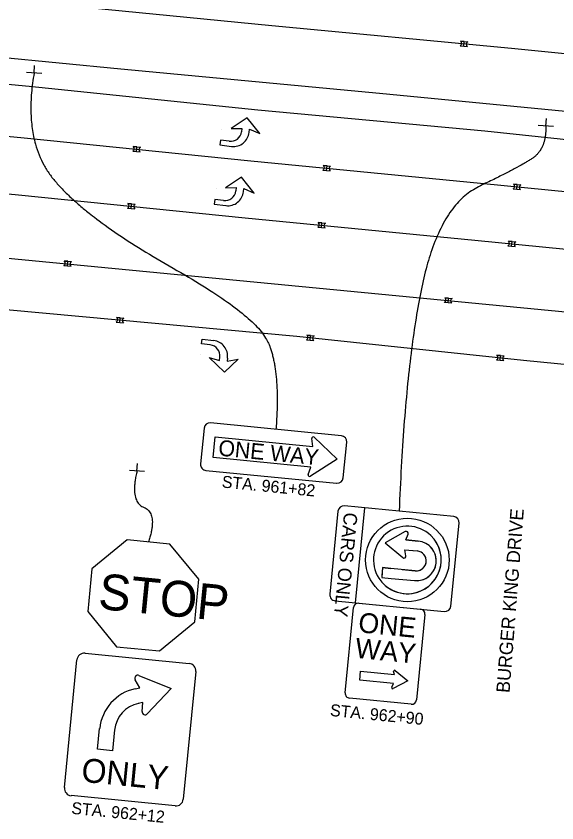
# Model space of a CAD drawing. Extents: x 1847379 to 1850904, y 217032 to 220169.
# Drawn here: x 1850312.9 to 1850426.1, y 218600.3 to 218769.3 of the extents above; entities that cross this region are included whole.
import ezdxf

# ---------------------------------------------------------------- set-up
doc = ezdxf.new("R2010")
doc.units = 0
for name, color, linetype in [('PM_P_Cells', 7, 'Continuous'), ('PM_P_Channelizing_Line', 7, 'Continuous'), ('PM_P_Edge_Line', 7, 'Continuous'), ('PM_P_Lane_Line', 7, 'Continuous'), ('SN_X_Public', 7, 'Continuous'), ('SN_X_Text', 7, 'Continuous')]:
    doc.layers.add(name, color=color, linetype=linetype)

msp = doc.modelspace()

# ---------------------------------------------------------------- linework, layer by layer
at = {"layer": 'PM_P_Cells'}
for p, q in [((1850406.66, 218764.02), (1850405.89, 218764.09)), ((1850405.89, 218764.09), (1850406.66, 218764.02)), ((1850406.57, 218763.04), (1850406.66, 218764.02)), ((1850406.66, 218764.02), (1850407.43, 218763.95)), ((1850405.81, 218763.11), (1850406.57, 218763.04)), ((1850405.81, 218763.11), (1850406.57, 218763.04)), ((1850406.57, 218763.04), (1850407.34, 218762.98)), ((1850361.22, 218748.03), (1850357.88, 218745.75)), ((1850363.88, 218744.7), (1850361.22, 218748.03)), ((1850355.94, 218745.64), (1850355.94, 218745.64)), ((1850357.88, 218745.75), (1850360.15, 218745.81)), ((1850360.15, 218745.81), (1850360.06, 218745.11)), ((1850361.66, 218744.96), (1850361.74, 218745.62)), ((1850361.74, 218745.62), (1850363.88, 218744.7)), ((1850363.88, 218744.7), (1850363.88, 218744.7)), ((1850338.15, 218741.92), (1850337.39, 218741.99)), ((1850337.39, 218741.99), (1850338.15, 218741.92)), ((1850355.66, 218743.33), (1850355.54, 218742.33)), ((1850355.54, 218742.33), (1850358, 218742.04)), ((1850357.51, 218743.11), (1850355.66, 218743.33)), ((1850337.3, 218741.01), (1850338.07, 218740.95)), ((1850337.3, 218741.01), (1850338.07, 218740.95)), ((1850338.07, 218740.95), (1850338.15, 218741.92)), ((1850338.07, 218740.95), (1850338.83, 218740.88)), ((1850338.15, 218741.92), (1850338.92, 218741.85)), ((1850377.1, 218737.05), (1850377.87, 218736.98)), ((1850377.1, 218737.05), (1850377.87, 218736.98)), ((1850377.96, 218737.95), (1850377.19, 218738.02)), ((1850377.19, 218738.02), (1850377.96, 218737.95)), ((1850377.87, 218736.98), (1850377.96, 218737.95)), ((1850377.87, 218736.98), (1850378.64, 218736.91)), ((1850377.96, 218737.95), (1850378.72, 218737.88)), ((1850360.03, 218735.61), (1850356.7, 218733.33)), ((1850362.69, 218732.27), (1850360.03, 218735.61)), ((1850417.77, 218734.05), (1850417, 218734.12)), ((1850417, 218734.12), (1850417.77, 218734.05)), ((1850417.68, 218733.08), (1850417.77, 218734.05)), ((1850417.77, 218734.05), (1850418.53, 218733.98)), ((1850354.75, 218733.22), (1850354.75, 218733.22)), ((1850356.7, 218733.33), (1850358.96, 218733.39)), ((1850358.96, 218733.39), (1850358.88, 218732.69)), ((1850360.47, 218732.54), (1850360.55, 218733.2)), ((1850360.55, 218733.2), (1850362.69, 218732.27)), ((1850362.69, 218732.27), (1850362.69, 218732.27)), ((1850416.91, 218733.15), (1850417.68, 218733.08)), ((1850416.91, 218733.15), (1850417.68, 218733.08)), ((1850417.68, 218733.08), (1850418.45, 218733.01)), ((1850354.47, 218730.91), (1850354.36, 218729.91)), ((1850356.32, 218730.68), (1850354.47, 218730.91)), ((1850336.22, 218729.06), (1850336.99, 218728.99)), ((1850336.22, 218729.06), (1850336.99, 218728.99)), ((1850337.07, 218729.97), (1850336.31, 218730.04)), ((1850336.31, 218730.04), (1850337.07, 218729.97)), ((1850336.99, 218728.99), (1850337.07, 218729.97)), ((1850336.99, 218728.99), (1850337.75, 218728.92)), ((1850337.07, 218729.97), (1850337.84, 218729.9)), ((1850354.36, 218729.91), (1850356.82, 218729.62)), ((1850376.02, 218725.1), (1850376.79, 218725.03)), ((1850376.02, 218725.1), (1850376.79, 218725.03)), ((1850376.88, 218726), (1850376.11, 218726.07)), ((1850376.11, 218726.07), (1850376.88, 218726)), ((1850376.79, 218725.03), (1850376.88, 218726)), ((1850376.88, 218726), (1850377.64, 218725.93)), ((1850376.79, 218725.03), (1850377.56, 218724.96)), ((1850416.69, 218722.1), (1850415.92, 218722.17)), ((1850415.92, 218722.17), (1850416.69, 218722.1)), ((1850416.6, 218721.13), (1850416.69, 218722.1)), ((1850416.69, 218722.1), (1850417.45, 218722.03)), ((1850415.83, 218721.2), (1850416.6, 218721.13)), ((1850415.83, 218721.2), (1850416.6, 218721.13)), ((1850416.6, 218721.13), (1850417.37, 218721.06)), ((1850322.87, 218717.05), (1850323.63, 218716.98)), ((1850322.87, 218717.05), (1850323.63, 218716.98)), ((1850323.72, 218717.96), (1850322.95, 218718.02)), ((1850322.95, 218718.02), (1850323.72, 218717.96)), ((1850323.63, 218716.98), (1850323.72, 218717.96)), ((1850323.63, 218716.98), (1850324.4, 218716.91)), ((1850323.72, 218717.96), (1850324.49, 218717.89)), ((1850403.39, 218710.27), (1850402.62, 218710.34)), ((1850402.62, 218710.34), (1850403.39, 218710.27)), ((1850403.3, 218709.3), (1850403.39, 218710.27)), ((1850403.39, 218710.27), (1850404.15, 218710.2)), ((1850402.53, 218709.37), (1850403.3, 218709.3)), ((1850402.53, 218709.37), (1850403.3, 218709.3)), ((1850403.3, 218709.3), (1850404.07, 218709.23)), ((1850333.82, 218705.24), (1850334.59, 218705.17)), ((1850333.82, 218705.24), (1850334.59, 218705.17)), ((1850334.68, 218706.15), (1850333.91, 218706.22)), ((1850333.91, 218706.22), (1850334.68, 218706.15)), ((1850334.59, 218705.17), (1850334.68, 218706.15)), ((1850334.59, 218705.17), (1850335.36, 218705.1)), ((1850334.68, 218706.15), (1850335.45, 218706.08)), ((1850351.68, 218700.66), (1850351.8, 218701.65)), ((1850351.8, 218701.65), (1850354.26, 218701.37)), ((1850373.65, 218701.52), (1850374.42, 218701.45)), ((1850373.65, 218701.52), (1850374.42, 218701.45)), ((1850374.5, 218702.42), (1850373.74, 218702.49)), ((1850373.74, 218702.49), (1850374.5, 218702.42)), ((1850374.42, 218701.45), (1850374.5, 218702.42)), ((1850374.42, 218701.45), (1850375.18, 218701.38)), ((1850374.5, 218702.42), (1850375.27, 218702.35)), ((1850353.53, 218700.44), (1850351.68, 218700.66)), ((1850351.42, 218698.34), (1850351.42, 218698.34)), ((1850414.28, 218698.2), (1850413.51, 218698.27)), ((1850413.51, 218698.27), (1850414.28, 218698.2)), ((1850414.19, 218697.23), (1850414.28, 218698.2)), ((1850414.28, 218698.2), (1850415.05, 218698.13)), ((1850356.48, 218694.74), (1850353.29, 218697.79)), ((1850353.29, 218697.79), (1850355.47, 218697.2)), ((1850355.47, 218697.2), (1850355.55, 218697.9)), ((1850359.36, 218697.43), (1850356.48, 218694.74)), ((1850357.14, 218697.68), (1850357.06, 218697.02)), ((1850357.06, 218697.02), (1850359.36, 218697.43)), ((1850359.36, 218697.43), (1850359.36, 218697.43)), ((1850413.43, 218697.3), (1850414.19, 218697.23)), ((1850413.43, 218697.3), (1850414.19, 218697.23)), ((1850414.19, 218697.23), (1850414.96, 218697.16))]:
    msp.add_line(p, q, dxfattribs=at)
for centre, radius, start, end in [((1850405.55, 218763.63), 0.576, 296.8063, 52.8586), ((1850405.55, 218763.63), 0.576, 296.8063, 52.8586), ((1850407.69, 218763.43), 0.576, 116.8063, 232.8586), ((1850357.78, 218745.39), 2.3, 263.1824, 353.1824), ((1850358.39, 218745.3), 3.28, 263.1824, 354.0909), ((1850337.04, 218741.53), 0.576, 296.8063, 52.8586), ((1850337.04, 218741.53), 0.576, 296.8063, 52.8586), ((1850339.18, 218741.34), 0.576, 116.8063, 232.8586), ((1850376.84, 218737.56), 0.576, 296.8063, 52.8586), ((1850376.84, 218737.56), 0.576, 296.8063, 52.8586), ((1850378.98, 218737.37), 0.576, 116.8063, 232.8586), ((1850416.65, 218733.66), 0.576, 296.8063, 52.8586), ((1850416.65, 218733.66), 0.576, 296.8063, 52.8586), ((1850418.79, 218733.47), 0.576, 116.8063, 232.8586), ((1850356.6, 218732.97), 2.3, 263.1824, 353.1824), ((1850357.21, 218732.88), 3.28, 263.1824, 354.0909), ((1850335.96, 218729.58), 0.576, 296.8063, 52.8586), ((1850335.96, 218729.58), 0.576, 296.8063, 52.8586), ((1850338.1, 218729.38), 0.576, 116.8063, 232.8586), ((1850375.76, 218725.61), 0.576, 296.8063, 52.8586), ((1850375.76, 218725.61), 0.576, 296.8063, 52.8586), ((1850377.9, 218725.42), 0.576, 116.8063, 232.8586), ((1850415.57, 218721.71), 0.576, 296.8063, 52.8586), ((1850415.57, 218721.71), 0.576, 296.8063, 52.8586), ((1850417.71, 218721.52), 0.576, 116.8063, 232.8586), ((1850322.61, 218717.57), 0.576, 296.8063, 52.8586), ((1850322.61, 218717.57), 0.576, 296.8063, 52.8586), ((1850324.75, 218717.37), 0.576, 116.8063, 232.8586), ((1850402.27, 218709.88), 0.576, 296.8063, 52.8586), ((1850402.27, 218709.88), 0.576, 296.8063, 52.8586), ((1850404.41, 218709.69), 0.576, 116.8063, 232.8586), ((1850333.56, 218705.76), 0.576, 296.8063, 52.8586), ((1850333.56, 218705.76), 0.576, 296.8063, 52.8586), ((1850335.7, 218705.56), 0.576, 116.8063, 232.8586), ((1850373.39, 218702.03), 0.576, 296.8063, 52.8586), ((1850373.39, 218702.03), 0.576, 296.8063, 52.8586), ((1850375.53, 218701.84), 0.576, 116.8063, 232.8586), ((1850353.27, 218698.16), 2.3, 353.453, 83.453), ((1850353.88, 218698.11), 3.28, 352.5446, 83.453), ((1850413.17, 218697.81), 0.576, 296.8063, 52.8586), ((1850413.17, 218697.81), 0.576, 296.8063, 52.8586), ((1850415.31, 218697.62), 0.576, 116.8063, 232.8586)]:
    msp.add_arc(centre, radius, start, end, dxfattribs=at)
at = {"layer": 'PM_P_Channelizing_Line'}
for points in [[(1850652.98, 218698.12), (1850615.27, 218701.75), (1850564.66, 218706.78), (1850513.12, 218712.05), (1850461.3, 218717.14), (1850408.88, 218722.34), (1850360.86, 218727.03), (1850313.39, 218731.82), (1850265.8, 218736.37), (1849979.48, 218762.27)], [(1850654.14, 218710.06), (1850616.44, 218713.69), (1850565.86, 218718.72), (1850514.32, 218723.99), (1850462.47, 218729.08), (1850410.06, 218734.29), (1850362.04, 218738.97), (1850314.56, 218743.77), (1850266.91, 218748.32), (1850234.59, 218751.24)], [(1850650.65, 218674.09), (1850566.02, 218682.53), (1850518.02, 218687.39), (1850471.03, 218692.07), (1850419.06, 218697.16), (1850371.65, 218702.19), (1850311.6, 218707.75), (1850264.65, 218712.06), (1850215.84, 218717), (1850171.13, 218721.51), (1850121.19, 218725.85), (1850066.37, 218730.8), (1850014.99, 218735.41), (1849965.69, 218739.72), (1849914.21, 218744.36), (1849896.49, 218746.14)]]:
    msp.add_lwpolyline(points, dxfattribs=at)
at = {"layer": 'PM_P_Edge_Line'}
for p, q in [((1850283.89, 218763.25), (1850334.84, 218758.27)), ((1850315.62, 218754.6), (1850267.46, 218759.14)), ((1850334.84, 218758.27), (1850388.94, 218753.21)), ((1850363.5, 218749.63), (1850315.62, 218754.6)), ((1850388.94, 218753.21), (1850440.13, 218748.21)), ((1850410.97, 218745.19), (1850363.5, 218749.63)), ((1850462.7, 218739.86), (1850410.97, 218745.19))]:
    msp.add_line(p, q, dxfattribs=at)
at = {"layer": 'PM_P_Lane_Line'}
msp.add_line((1849881.96, 218760.04), (1850650.78, 218685.87), dxfattribs=at)
msp.add_lwpolyline([(1849608.99, 218828.81), (1849660.31, 218825.18), (1849710.18, 218821.58), (1849761.09, 218817.87), (1849808.06, 218814.41), (1849858.45, 218811.1), (1849907.69, 218807.67), (1849958.4, 218803.79), (1850015.55, 218799.15), (1850068.16, 218794.66), (1850119.07, 218790.16), (1850168.5, 218785.91), (1850217.76, 218781.65), (1850267.02, 218777.03), (1850317.3, 218772.15), (1850366.38, 218767.35), (1850416.59, 218762.59), (1850466.65, 218757.55), (1850517.86, 218752.55), (1850566.57, 218747.88), (1850616.29, 218742.91), (1850664.9, 218737.75)], dxfattribs=at)
at = {"layer": 'SN_X_Public'}
for p, q in [((1850316.66, 218757.39), (1850316.76, 218758.98)), ((1850318.25, 218757.28), (1850315.06, 218757.49)), ((1850423.77, 218746.3), (1850423.87, 218747.9)), ((1850425.36, 218746.19), (1850422.17, 218746.41)), ((1850354.14, 218676.85), (1850354.56, 218681.2)), ((1850354.56, 218681.2), (1850375.02, 218679.19)), ((1850375.02, 218679.19), (1850374.77, 218680.82)), ((1850375.3, 218681.09), (1850380.06, 218676.49)), ((1850374.59, 218674.83), (1850354.14, 218676.85)), ((1850380.06, 218676.49), (1850374.49, 218672.92)), ((1850338.19, 218674.01), (1850338.3, 218675.6)), ((1850374.03, 218673.29), (1850374.59, 218674.83)), ((1850339.79, 218673.9), (1850336.59, 218674.11)), ((1850404.47, 218664.49), (1850381.62, 218666.74)), ((1850385.81, 218666.33), (1850383.85, 218646.42)), ((1850380.26, 218665.62), (1850378.54, 218648.2)), ((1850394.34, 218661.33), (1850390.11, 218659)), ((1850336.14, 218659.63), (1850328.76, 218653.57)), ((1850345.1, 218658.74), (1850336.14, 218659.63)), ((1850394.43, 218659.62), (1850394.93, 218660.8)), ((1850394.43, 218659.62), (1850397.06, 218659.36)), ((1850351.15, 218651.36), (1850345.1, 218658.74)), ((1850390.11, 218659), (1850393.81, 218655.88)), ((1850394.22, 218657.55), (1850396.85, 218657.29)), ((1850394.48, 218656.28), (1850394.22, 218657.55)), ((1850328.76, 218653.57), (1850327.88, 218644.61)), ((1850389.6, 218653.81), (1850389.4, 218651.74)), ((1850389.6, 218653.81), (1850389.43, 218652.08)), ((1850389.6, 218653.81), (1850391.33, 218653.64)), ((1850391.33, 218653.64), (1850389.6, 218653.81)), ((1850393.68, 218653.41), (1850396.44, 218653.14)), ((1850350.27, 218642.41), (1850351.15, 218651.36)), ((1850391.4, 218651.54), (1850396.24, 218651.07)), ((1850379.66, 218646.84), (1850402.51, 218644.59)), ((1850384.62, 218646.35), (1850397.56, 218645.08)), ((1850327.88, 218644.61), (1850333.93, 218637.23)), ((1850381.76, 218627.54), (1850383.53, 218645.45)), ((1850398.45, 218643.98), (1850396.69, 218626.07)), ((1850342.89, 218636.35), (1850350.27, 218642.41)), ((1850333.93, 218637.23), (1850342.89, 218636.35)), ((1850392.24, 218632.24), (1850394.88, 218630.1)), ((1850338.6, 218631.2), (1850345.34, 218628.45)), ((1850384.82, 218630.22), (1850385, 218632.09)), ((1850385, 218632.09), (1850392.07, 218631.4)), ((1850392.07, 218631.38), (1850391.91, 218632.04)), ((1850338.78, 218628.63), (1850337.82, 218630.31)), ((1850391.87, 218629.53), (1850384.82, 218630.22)), ((1850391.51, 218628.72), (1850391.87, 218629.53)), ((1850394.88, 218630.1), (1850391.8, 218628.45)), ((1850337.81, 218628.42), (1850338.78, 218628.63)), ((1850345.34, 218628.45), (1850340.34, 218623.16)), ((1850339.44, 218625.57), (1850338.47, 218625.36)), ((1850339.27, 218623.65), (1850339.44, 218625.57)), ((1850395.6, 218625.17), (1850382.66, 218626.45)), ((1850329.95, 218615.73), (1850330.38, 218620.08)), ((1850333.49, 218619.78), (1850333.06, 218615.42)), ((1850333.06, 218615.42), (1850329.95, 218615.73))]:
    msp.add_line(p, q, dxfattribs=at)
for points in [[(1850352.23, 218683), (1850351.49, 218675.54)], [(1850380.96, 218681.43), (1850353.6, 218684.12)], [(1850381.35, 218672.6), (1850382.08, 218680.06)], [(1850352.62, 218674.17), (1850379.98, 218671.48)], [(1850403.88, 218645.71), (1850405.59, 218663.13)], [(1850394.34, 218661.33), (1850390.11, 218659), (1850393.81, 218655.88)], [(1850397.06, 218659.36), (1850394.43, 218659.62), (1850394.93, 218660.8)], [(1850394.48, 218656.28), (1850394.22, 218657.55), (1850395.89, 218657.38), (1850395.89, 218657.38)], [(1850396.44, 218653.14), (1850391.33, 218653.64)], [(1850389.4, 218651.74), (1850391.4, 218651.54), (1850396.24, 218651.07)], [(1850327.33, 218635.87), (1850349.1, 218633.73)], [(1850322.99, 218607.73), (1850325.62, 218634.47)], [(1850350.5, 218632.02), (1850347.87, 218605.28)], [(1850346.16, 218603.88), (1850324.39, 218606.02)]]:
    msp.add_lwpolyline(points, dxfattribs=at)
msp.add_circle((1850394.78, 218655.4), 8.75, dxfattribs=at)
for centre, radius, start, end in [((1850353.47, 218682.88), 1.25, 84.3781, 174.3781), ((1850375.08, 218680.87), 0.314, 46.0361, 188.5955), ((1850380.84, 218680.18), 1.25, 354.3781, 84.3781), ((1850352.74, 218675.41), 1.25, 174.3781, 264.3781), ((1850374.32, 218673.18), 0.314, 160.1349, 302.7507), ((1850380.11, 218672.72), 1.25, 264.3781, 354.3781), ((1850381.5, 218665.5), 1.25, 84.3781, 174.3781), ((1850404.35, 218663.25), 1.25, 354.3781, 84.3781), ((1850394.78, 218655.4), 7.08, 46.1345, 212.6218), ((1850394.55, 218660.97), 0.417, 337.0163, 118.8944), ((1850394.55, 218660.97), 0.417, 337.0163, 118.8944), ((1850394.78, 218655.4), 7.08, 212.6218, 46.1345), ((1850394.78, 218655.4), 7.08, 226.1345, 32.6218), ((1850396.65, 218655.21), 4.17, 264.3781, 84.3781), ((1850396.65, 218655.21), 4.17, 264.3781, 46.1662), ((1850394.08, 218656.2), 0.417, 229.8619, 11.74), ((1850394.08, 218656.2), 0.417, 229.8619, 253.6108), ((1850394.08, 218656.2), 0.417, 229.8619, 253.6108), ((1850394.08, 218656.2), 0.417, 5.1455, 11.74), ((1850394.08, 218656.2), 0.417, 5.1455, 11.74), ((1850396.65, 218655.21), 2.08, 264.3781, 84.3781), ((1850396.65, 218655.21), 2.08, 264.3781, 53.0521), ((1850379.79, 218648.08), 1.25, 174.3781, 264.3781), ((1850384.52, 218645.35), 1, 84.3781, 174.3781), ((1850402.63, 218645.83), 1.25, 264.3781, 354.3781), ((1850397.46, 218644.08), 1, 354.3781, 84.3781), ((1850327.18, 218634.32), 1.56, 84.3781, 174.3781), ((1850348.95, 218632.18), 1.56, 354.3781, 84.3781), ((1850392.11, 218632.08), 0.208, 50.8022, 193.4415), ((1850338.37, 218630.62), 0.625, 67.8128, 209.5846), ((1850391.7, 218628.63), 0.208, 156.4547, 298.1036), ((1850339.82, 218619.15), 9.48, 102.2356, 174.3781), ((1850382.76, 218627.44), 1, 174.3781, 264.3781), ((1850339.82, 218619.15), 6.35, 102.2394, 174.3781), ((1850395.69, 218626.17), 1, 264.3781, 354.3781), ((1850339.89, 218623.59), 0.625, 174.8521, 316.6239), ((1850324.55, 218607.57), 1.56, 174.3781, 264.3781), ((1850346.32, 218605.43), 1.56, 264.3781, 354.3781)]:
    msp.add_arc(centre, radius, start, end, dxfattribs=at)
for points in [[(1850423.77, 218746.3), (1850423.84, 218741.46), (1850418.05, 218737.61), (1850401.37, 218729.57), (1850394.27, 218695.84), (1850393.05, 218665.62)], [(1850338.19, 218674.01), (1850336.65, 218667.6), (1850342.59, 218665.25), (1850340.62, 218659.18)]]:
    msp.add_open_spline(points, degree=2, dxfattribs=at)
at = {"layer": 'SN_X_Text'}
msp.add_open_spline([(1850316.66, 218757.39), (1850314.09, 218742.76), (1850328.24, 218726.45), (1850363.05, 218706.73), (1850368.22, 218695.19), (1850367.28, 218682.78)], degree=2, dxfattribs=at)

# ---------------------------------------------------------------- texts
at = {"layer": 'SN_X_Public'}
for s, height, rotation, p in [('ONE WAY', 3.333, 354.3781, (1850355.1, 218677.28)), ('STA. 961+82', 2.5, 354.3781, (1850355.86, 218670.59)), ('BURGER KING DRIVE', 2.8, 85.5355, (1850416.16, 218627.47)), ('CARS ONLY', 2.839, 264.3781, (1850381.55, 218665.45)), ('STOP', 7.5, 354.3781, (1850329.9, 218645.17)), ('ONE', 4.172, 354.3781, (1850384.37, 218640.27)), ('WAY', 4.172, 354.3781, (1850383.71, 218634.92)), ('STA. 962+90', 2.5, 354.3781, (1850378.51, 218622.74)), ('ONLY', 5, 354.3781, (1850326.4, 218608.96))]:
    msp.add_text(s, height=height, rotation=rotation, dxfattribs=at).set_placement(p)
at = {"layer": 'SN_X_Text'}
msp.add_text('STA. 962+12', height=2.5, rotation=354.3781, dxfattribs=at).set_placement((1850324.37, 218602.23))

doc.saveas('drawing.dxf')
